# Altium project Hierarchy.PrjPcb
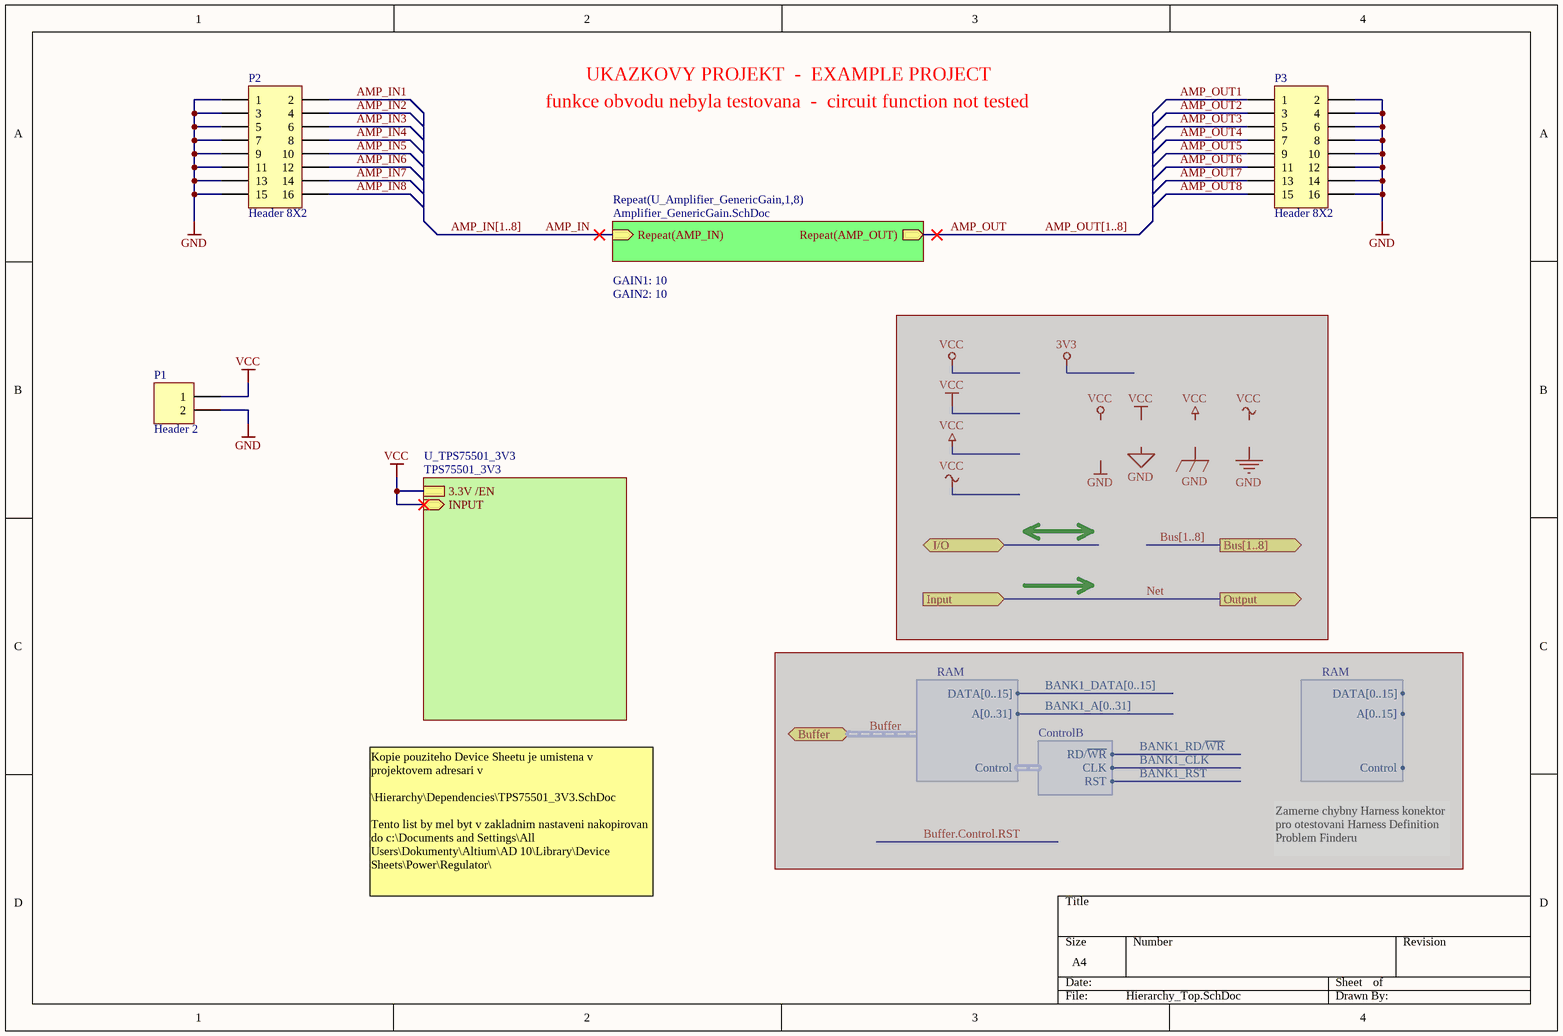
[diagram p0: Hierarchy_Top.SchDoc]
2 sheets, 75 parts. Net scope: hierarchical (ports join the sheet entries above them; power ports are global).
Board file: Amp_Module.PcbDoc
Sheets:
  Hierarchy_Top.SchDoc
    U_Amplifier_GenericGain1 = Amplifier_GenericGain.SchDoc
    U_Amplifier_GenericGain2 = Amplifier_GenericGain.SchDoc
    U_Amplifier_GenericGain3 = Amplifier_GenericGain.SchDoc
    U_Amplifier_GenericGain4 = Amplifier_GenericGain.SchDoc
    U_Amplifier_GenericGain5 = Amplifier_GenericGain.SchDoc
    U_Amplifier_GenericGain6 = Amplifier_GenericGain.SchDoc
    U_Amplifier_GenericGain7 = Amplifier_GenericGain.SchDoc
    U_Amplifier_GenericGain8 = Amplifier_GenericGain.SchDoc

## Sheet Hierarchy_Top.SchDoc
size A4; DocumentNumber: 1; SheetNumber: 1; SheetTotal: 3

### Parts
P1  Header 2  [HDR1X2]
P2  Header 8X2  [HDR2X8]
P3  Header 8X2  [HDR2X8]

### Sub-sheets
Repeat(U_Amplifier_GenericGain,1,8) = Amplifier_GenericGain.SchDoc: Repeat(AMP_IN) (in), Repeat(AMP_OUT) (out)  | GAIN1: 10; GAIN2: 10
U_TPS75501_3V3 = TPS75501_3V3 (file not in this document): 3.3V /EN, INPUT (in)

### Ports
Buffer (harness RAM), Bus[1..8] (out), I/O (bidir), Input (in), Output (out)

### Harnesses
RAM: DATA[0..15], A[0..31], Control
ControlB: RD/~{WR}, CLK, RST
RAM: DATA[0..15], A[0..15], Control

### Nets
GND: P1.2 P2.1 P2.3 P2.5 P2.7 P2.9 P2.11 P2.13 P2.15 P3.2 P3.4 P3.6 P3.8 P3.10 P3.12 P3.14 P3.16
VCC: P1.1 ; sheet U_TPS75501_3V3/3.3V /EN, sheet U_TPS75501_3V3/INPUT
AMP_IN1: P2.2
AMP_IN2: P2.4
AMP_IN3: P2.6
AMP_IN4: P2.8
AMP_IN5: P2.10
AMP_IN6: P2.12
AMP_IN7: P2.14
AMP_IN8: P2.16
AMP_OUT1: P3.1
AMP_OUT2: P3.3
AMP_OUT3: P3.5
AMP_OUT4: P3.7
AMP_OUT5: P3.9
AMP_OUT6: P3.11
AMP_OUT7: P3.13
AMP_OUT8: P3.15

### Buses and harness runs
bus AMP_IN[1..8]
bus AMP_OUT[1..8]

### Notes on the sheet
- funkce obvodu nebyla testovana  -  circuit function not tested
- UKAZKOVY PROJEKT  -  EXAMPLE PROJECT
- Zamerne chybny Harness konektor pro otestovani Harness Definition Problem Finderu
- Kopie pouziteho Device Sheetu je umistena v projektovem adresari v
  \Hierarchy\Dependencies\TPS75501_3V3.SchDoc
  Tento list by mel byt v zakladnim nastaveni nakopirovan do c:\Documents and Settings\All Users\Dokumenty\Altium\AD 10\Library\Device Sheets\Power\Regulator\

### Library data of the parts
P1 = Header 2: Header, 2-Pin
P2 P3 = Header 8X2: Header, 8-Pin, Dual row

## Sheet Amplifier_GenericGain.SchDoc
size A4; DocumentNumber: 2; SheetNumber: 2; SheetTotal: 3
Used 8 times, as channels U_Amplifier_GenericGain1, U_Amplifier_GenericGain2, U_Amplifier_GenericGain3, U_Amplifier_GenericGain4, U_Amplifier_GenericGain5, U_Amplifier_GenericGain6, U_Amplifier_GenericGain7, U_Amplifier_GenericGain8. Parts and nets are listed once, with the designators drawn on the sheet.
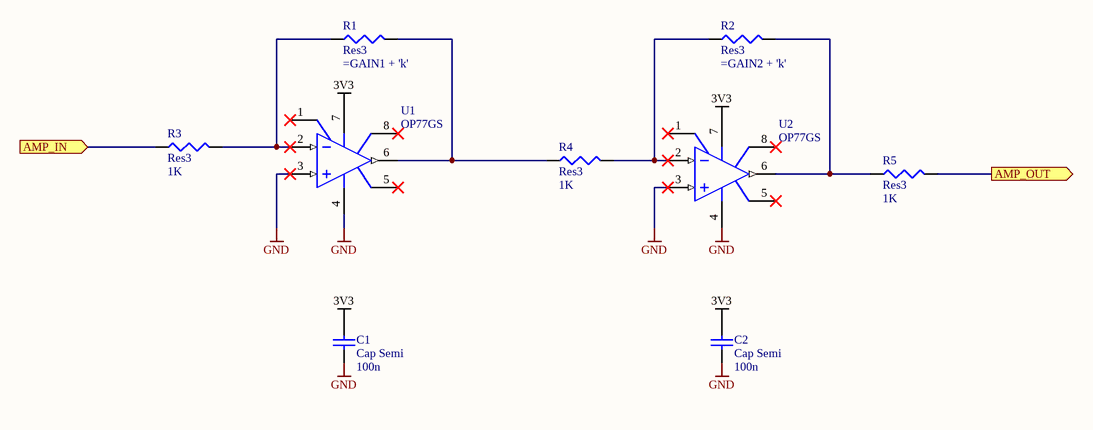
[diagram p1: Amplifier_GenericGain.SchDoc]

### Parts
C1  Cap Semi  value 100n  [C1206]
C2  Cap Semi  value 100n  [C1206]
R1  Res3  [J1-0603]
R2  Res3  [J1-0603]
R3  Res3  value 1K  [J1-0603]
R4  Res3  value 1K  [J1-0603]
R5  Res3  value 1K  [J1-0603]
U1  OP77GS  [SO-8_N]
U2  OP77GS  [SO-8_N]

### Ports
AMP_IN (in), AMP_OUT (out)

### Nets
3V3: C1.1 C2.1 U1.7(V+) U2.7(V+)
GND: C1.2 C2.2 U1.3(IN+) U1.4(V-) U2.3(IN+) U2.4(V-)
AMP_IN: R3.1 ; port AMP_IN
AMP_OUT: R5.2 ; port AMP_OUT
NetR1_1: R1.1 R3.2 U1.2(IN-)
NetR1_2: R1.2 R4.1 U1.6(OUT)
NetR2_1: R2.1 R4.2 U2.2(IN-)
NetR2_2: R2.2 R5.1 U2.6(OUT)

Not connected (* = marked no-connect by the designer): U1 1(VOSTRIM)* 5(NC)* 8(VOSTRIM)*; U2 1(VOSTRIM)* 5(NC)* 8(VOSTRIM)*

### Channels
U_Amplifier_GenericGain1: ports AMP_IN=AMP_IN1 AMP_OUT=AMP_OUT1
U_Amplifier_GenericGain2: designators C1=C3 C2=C4 R1=R6 R2=R7 R3=R8 R4=R9 R5=R10 U1=U3 U2=U4; ports AMP_IN=AMP_IN2 AMP_OUT=AMP_OUT2
U_Amplifier_GenericGain3: designators C1=C5 C2=C6 R1=R11 R2=R12 R3=R13 R4=R14 R5=R15 U1=U5 U2=U6; ports AMP_IN=AMP_IN3 AMP_OUT=AMP_OUT3
U_Amplifier_GenericGain4: designators C1=C7 C2=C8 R1=R16 R2=R17 R3=R18 R4=R19 R5=R20 U1=U7 U2=U8; ports AMP_IN=AMP_IN4 AMP_OUT=AMP_OUT4
U_Amplifier_GenericGain5: designators C1=C9 C2=C10 R1=R21 R2=R22 R3=R23 R4=R24 R5=R25 U1=U9 U2=U10; ports AMP_IN=AMP_IN5 AMP_OUT=AMP_OUT5
U_Amplifier_GenericGain6: designators C1=C11 C2=C12 R1=R26 R2=R27 R3=R28 R4=R29 R5=R30 U1=U11 U2=U12; ports AMP_IN=AMP_IN6 AMP_OUT=AMP_OUT6
U_Amplifier_GenericGain7: designators C1=C13 C2=C14 R1=R31 R2=R32 R3=R33 R4=R34 R5=R35 U1=U13 U2=U14; ports AMP_IN=AMP_IN7 AMP_OUT=AMP_OUT7
U_Amplifier_GenericGain8: designators C1=C15 C2=C16 R1=R36 R2=R37 R3=R38 R4=R39 R5=R40 U1=U15 U2=U16; ports AMP_IN=AMP_IN8 AMP_OUT=AMP_OUT8

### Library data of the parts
C1 C2 = Cap Semi: Capacitor (Semiconductor SIM Model)
R1-R5 = Res3: Resistor
U1 U2 = OP77GS: Ultra-Low Offset Voltage Operational Amplifier; Note: Pin 5 is not connected.

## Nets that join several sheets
3V3: U_Amplifier_GenericGain1 (C1.1 C2.1 U1.7 U2.7), U_Amplifier_GenericGain2 (C3.1 C4.1 U3.7 U4.7), U_Amplifier_GenericGain3 (C5.1 C6.1 U5.7 U6.7), U_Amplifier_GenericGain4 (C7.1 C8.1 U7.7 U8.7), U_Amplifier_GenericGain5 (C9.1 C10.1 U9.7 U10.7), U_Amplifier_GenericGain6 (C11.1 C12.1 U11.7 U12.7), U_Amplifier_GenericGain7 (C13.1 C14.1 U13.7 U14.7), U_Amplifier_GenericGain8 (C15.1 C16.1 U15.7 U16.7)
GND: Hierarchy_Top (17 pins), U_Amplifier_GenericGain1 (6 pins), U_Amplifier_GenericGain2 (6 pins), U_Amplifier_GenericGain3 (6 pins), U_Amplifier_GenericGain4 (6 pins), U_Amplifier_GenericGain5 (6 pins), U_Amplifier_GenericGain6 (6 pins), U_Amplifier_GenericGain7 (6 pins), U_Amplifier_GenericGain8 (6 pins)
AMP_IN1: Hierarchy_Top (P2.2), U_Amplifier_GenericGain1 (R3.1)
AMP_IN2: Hierarchy_Top (P2.4), U_Amplifier_GenericGain2 (R8.1)
AMP_IN3: Hierarchy_Top (P2.6), U_Amplifier_GenericGain3 (R13.1)
AMP_IN4: Hierarchy_Top (P2.8), U_Amplifier_GenericGain4 (R18.1)
AMP_IN5: Hierarchy_Top (P2.10), U_Amplifier_GenericGain5 (R23.1)
AMP_IN6: Hierarchy_Top (P2.12), U_Amplifier_GenericGain6 (R28.1)
AMP_IN7: Hierarchy_Top (P2.14), U_Amplifier_GenericGain7 (R33.1)
AMP_IN8: Hierarchy_Top (P2.16), U_Amplifier_GenericGain8 (R38.1)
AMP_OUT1: Hierarchy_Top (P3.1), U_Amplifier_GenericGain1 (R5.2)
AMP_OUT2: Hierarchy_Top (P3.3), U_Amplifier_GenericGain2 (R10.2)
AMP_OUT3: Hierarchy_Top (P3.5), U_Amplifier_GenericGain3 (R15.2)
AMP_OUT4: Hierarchy_Top (P3.7), U_Amplifier_GenericGain4 (R20.2)
AMP_OUT5: Hierarchy_Top (P3.9), U_Amplifier_GenericGain5 (R25.2)
AMP_OUT6: Hierarchy_Top (P3.11), U_Amplifier_GenericGain6 (R30.2)
AMP_OUT7: Hierarchy_Top (P3.13), U_Amplifier_GenericGain7 (R35.2)
AMP_OUT8: Hierarchy_Top (P3.15), U_Amplifier_GenericGain8 (R40.2)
